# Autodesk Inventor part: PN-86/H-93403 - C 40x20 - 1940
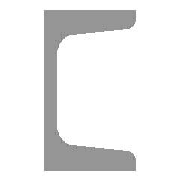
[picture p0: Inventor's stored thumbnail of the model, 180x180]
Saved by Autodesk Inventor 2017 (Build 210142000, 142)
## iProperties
_CCFamilyMember: 20
_CCFamilyDisplayName: PN-86/H-93403 - Ceownik
_FrameMemberDoc: Frame Member File
_Version: 15.0.0
_GetPNFromCC: 1
Created: 2016-02
Part Number: PN-86/H-93403 - C 40x20 - 1940
Material: Stal, miękka
Description: Ceownik
Document SubType Name: Modeling
Standard: PN
Designer: X
Standards Organization: PN
Language: pl-PL
Size Designation: C 40x20
Categories: <MemberInstance><Categories><Category DisplayName="Kształtowniki konstrukcyjne" InternalName="089c4875-fa83-4c05-b084-43b9cc11f5ed" Mnemonic="GRDR"><CategoryPar
Stock Number: C 40x20
Density: 7.85 g/cm^3
Appearance: Częściowo polerowana
IsCustomPart: 1
G_L: 1940,000 mm
G_W: 20,000 mm
G_H: 40,000 mm
Author: X
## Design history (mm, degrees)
node "Płaszczyzna początkowa"
node "Płaszczyzna końcowa"
sketch "Szkic"
  geometry: L1 (0, 0)-(0, 20); L2 (0, 20)-(20, 20); L3 (20, 20)-(20, 16.908); L4 (17.699, 14.416)-(9.601, 13.768); L5 (5, 8.784)-(5, 0); L6 (5, 0)-(0, 0); L7 (12.5, 20)-(12.5, 14); L8 (20, 14.6)-(20, 14); L9 (20, 14)-(12.5, 14); L10 (0, 15)-(0, -27); L11 (-5.539, 0)-(16.007, 0); L12 (0, 0)-(0, -20); L13 (0, -20)-(20, -20); L14 (20, -20)-(20, -16.908); L15 (17.699, -14.416)-(9.601, -13.768); L16 (5, -8.784)-(5, 0); L17 (0, 26.4)-(0, -35.9) reference; L18 (-13.764, 0)-(43.809, 0) reference; A1 r 5 centre (10, 8.784) between (9.601, 13.768) and (5, 8.784); A2 r 5 centre (10, -8.784) between (5, -8.784) and (9.601, -13.768); A3 r 2.5 centre (17.5, 16.908) between (17.699, 14.416) and (20, 16.908); A4 r 2.5 centre (17.5, -16.908) between (20, -16.908) and (17.699, -14.416); 5 further points
  constraints: 32 end point, 12 point on line, 8 point on circle, 8 tangent, 6 symmetric about line, 4 centre point, 4 parallel, 3 collinear, 3 perpendicular, 2 equal radius, 5 other
  dimensions: "d0" = 5 distance between parallel lines of L1 L5 (= G_T); "d1" = 20 distance between parallel lines of L6 L2 (= 0.5 x G_H); "d2" = 20 distance between parallel lines of L3 L1 (= G_W); "d3" = 6 distance of L2.end L8.end (= G_T1); "d4" = 7.5 distance of L7.start L2.end (= G_C); "d5" = 0.6 distance of L8.start L8.end (computed from G_NG, G_C); "d23" = 5 radius of A1 (= G_IR); "d24" = 2.5 radius of A3 (= G_ER); "d25" = 0 distance between parallel lines of L10 L12 (computed from ex)
extrude "Bryła" new body sketch "Szkic" stored distance "d6" = 1940 (= G_L); taper "d7" = 0 deg
node "Driven Length"
  sketch "Sketch3"
    geometry: L1 (0, 0)-(10, 0) reference
    constraints: 2 end point, 1 horizontal
  workplane "Work Plane3"
  sketch "Sketch4"
    geometry: L1 (-2, 0)-(12, 0) reference; L2 (-2, 1940)-(12, 1940) reference
    dimensions: "d29" = 1940 distance between parallel lines of L1 L2 (derived)
body "Solid1"
other parameters: "G_W" = 20 [user parameter; used in 1 equation term], "G_H" = 40 [user parameter; used in 1 equation term], "G_T" = 5 [user parameter; used in 1 equation term], "G_T1" = 6 [user parameter; used in 1 equation term], "G_NG" = 0.8 [user parameter; used in 1 equation term], "G_ER" = 2.5 [user parameter; used in 1 equation term], "G_IR" = 5 [user parameter; used in 1 equation term], "G_C" = 7.5 [user parameter; used in 2 equation terms], "G_L" = 1940 (= d29) [user parameter; used in 1 equation term], "ex" = 0 [user parameter; used in 1 equation term], "G_OFFSET_START" = 0 [user parameter; used in 1 equation term], "G_OFFSET_END" = 0 [user parameter; used in 1 equation term], "d26" = 0 (computed from G_OFFSET_START), "d28" = 90 deg
